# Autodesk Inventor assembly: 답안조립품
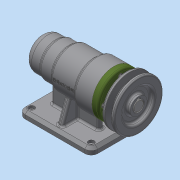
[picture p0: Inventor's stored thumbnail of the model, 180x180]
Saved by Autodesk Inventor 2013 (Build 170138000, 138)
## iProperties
Created: 2016-06
Part Number: 답안조립품
Document SubType Name: Assembly
Designer: dgall
Author: dgall
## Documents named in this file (12)
- C:\Users\dgall\Desktop\460607V1017\답안조립품.iam
- C:\Users\dgall\Desktop\460607V1017\1.본체.ipt
- C:\Users\dgall\Desktop\460607V1017\V벨트풀리.ipt
- C:\Users\dgall\Desktop\460607V1017\멈춤나사 M3x8.ipt
- C:\Users\dgall\Desktop\460607V1017\베어링 6004.ipt
- C:\Users\dgall\Desktop\460607V1017\베어링 51202.ipt
- C:\Users\dgall\Desktop\460607V1017\볼트 M4 x 12.ipt
- C:\Users\dgall\Desktop\460607V1017\어댑터슬리브.ipt
- C:\Users\dgall\Desktop\460607V1017\오일 실.ipt
- C:\Users\dgall\Desktop\460607V1017\축.ipt
- C:\Users\dgall\Desktop\460607V1017\커버.ipt
- C:\Users\dgall\Desktop\460607V1017\키 5 x 5 x 16.ipt
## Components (7 placed, 3 different names)
1. 1.본체:1 — 각도:1
2. V벨트풀리:1 — 플러쉬:1
3. ISO 4762 M4 x 12:1
4. ISO 4762 M4 x 12:2
5. ISO 4762 M4 x 12:3
6. ISO 4762 M4 x 12:4
7. ISO 4762 M4 x 12:5
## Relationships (2: Flush 1, Angle 1)
- 플러쉬:1 [Flush]: V벨트풀리:1
- 각도:1 [Angle]: 1.본체:1
